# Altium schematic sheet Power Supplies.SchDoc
size 431 x 279 mm; Organization: ORGANIZATION; Address1: ADDRESS 1; Address2: ADDRESS 2; Address3: ADDRESS 3; Address4: ADDRESS 4; Revision: -; ENG_APP_DATE: --/--/--; DSN_APP_DATE: --/--/--; CHK_APP_DATE: --/--/--
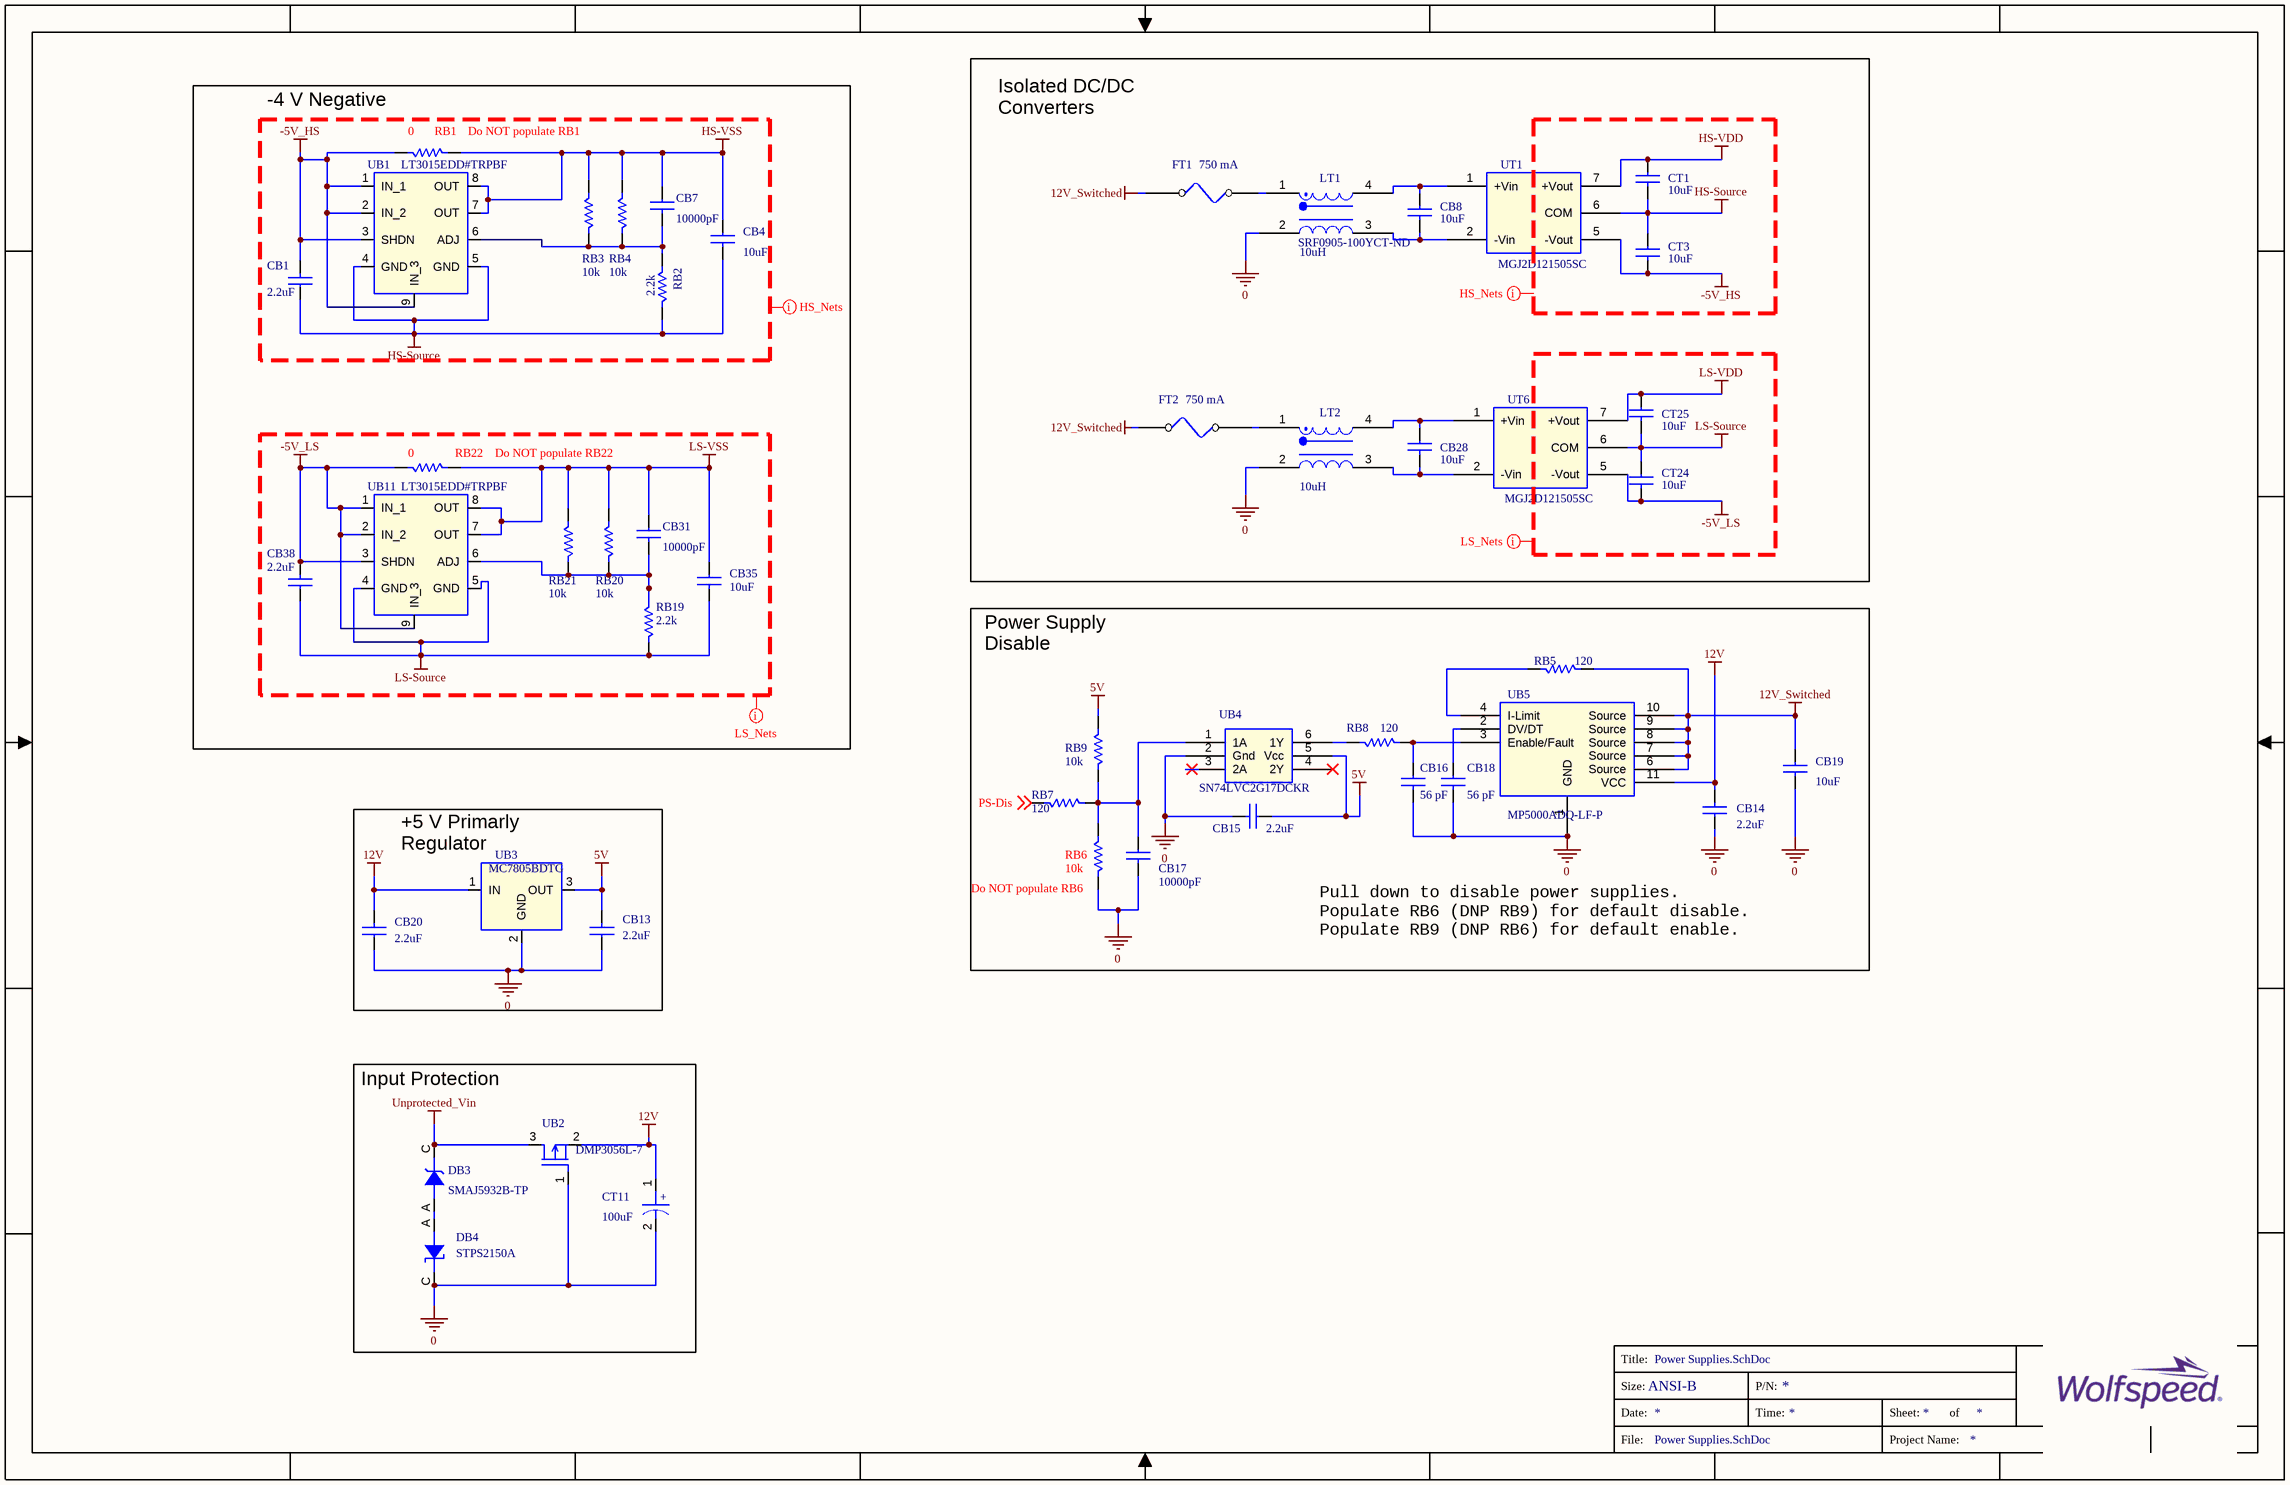
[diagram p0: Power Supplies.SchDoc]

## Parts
CB1  2.2uF  [CAPC1608X90N]
CB4  10uF  [C_1206]
CB7  10000pF  [CAPC1608X90N]
CB8  10uF  [C_1206]
CB13  2.2uF  [CAPC1608X90N]
CB14  2.2uF  [CAPC1608X90N]
CB15  2.2uF  [CAPC1608X90N]
CB16  56 pF  [CAPC1608X90N]
CB17  10000pF  [CAPC1608X90N]
CB18  56 pF  [CAPC1608X90N]
CB19  10uF  [C_1206]
CB20  2.2uF  [CAPC1608X90N]
CB28  10uF  [C_1206]
CB31  10000pF  [CAPC1608X90N]
CB35  10uF  [C_1206]
CB38  2.2uF  [CAPC1608X90N]
CT1  10uF  [C_1206]
CT3  10uF  [C_1206]
CT11  100uF  [CAP_EEE1HA101UP]
CT24  10uF  [C_1206]
CT25  10uF  [C_1206]
DB3  SMAJ5932B-TP  [DIOM4426X24N_DB3]
DB4  STPS2150A  [DIOM4326X26N_DB4]
FT1  750 mA  [FUSE_SMD_SSQ2410]
FT2  750 mA  [FUSE_SMD_SSQ2410]
LT1  10uH  Supplier Part Number 1: SRF0905-100YCT-ND  [SRF0905]
LT2  10uH  [SRF0905]
RB1  0  [RES_2012_SAM]
RB2  2.2k  [RESC1608X55N]
RB3  10k  [RESC1608X55N]
RB4  10k  [RESC1608X55N]
RB5  120  [RESC1608X55N]
RB6  10k  [RESC1608X55N]
RB7  120  [RESC1608X55N]
RB8  120  [RESC1608X55N]
RB9  10k  [RESC1608X55N]
RB19  2.2k  [RESC1608X55N]
RB20  10k  [RESC1608X55N]
RB21  10k  [RESC1608X55N]
RB22  0  [RES_2012_SAM]
UB1  LT3015EDD#TRPBF  [8-WDFN_Exposed_Pad]
UB2  DMP3056L-7  [SOT_23_3]
UB3  MC7805BDTG  [DPAK-3]
UB4  SN74LVC2G17DCKR  [SOT65P210X110-6N_UB4]
UB5  MP5000ADQ-LF-P  [SON50P300X300X100-11N]
UB11  LT3015EDD#TRPBF  [8-WDFN_Exposed_Pad]
UT1  MGJ2D121505SC  [MGJ2D121505SC]
UT6  MGJ2D121505SC  [MGJ2D121505SC]

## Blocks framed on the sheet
Do NOT populate RB6: CB14-CB19 RB5-RB9 UB4 UB5
Input Protection: CT11 DB3 DB4 UB2

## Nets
0: CB13.1 CB14.1 CB15.2 CB16.2 CB17.2 CB18.2 CB19.2 CB20.1 CT11.2 DB4.C LT1.2 LT2.2 RB6.2 UB2.1(G) UB3.2(GND) UB4.2(Gnd) UB5.1(GND)
5V: CB13.2 CB15.1 RB9.1 UB3.3(OUT) UB4.5(Vcc)
12V: CB14.2 CB20.2 CT11.1 UB2.2(S) UB3.1(IN) UB5.11(VCC)
12V_Switched: CB19.1 FT1.1 FT2.1 RB5.1 UB5.6(Source) UB5.7(Source) UB5.8(Source) UB5.9(Source) UB5.10(Source)
-5V_HS: CB1.2 CT3.2 RB1.1 UB1.1(IN_1) UB1.2(IN_2) UB1.3(SHDN) UB1.9(IN_3) UT1.5(-Vout)
-5V_LS: CB38.2 CT24.2 RB22.1 UB11.1(IN_1) UB11.2(IN_2) UB11.3(SHDN) UB11.9(IN_3) UT6.5(-Vout)
HS-Source: CB1.1 CB4.2 CT1.2 CT3.1 RB2.2 UB1.4(GND) UB1.5(GND) UT1.6(COM)
HS-VDD: CT1.1 UT1.7(+Vout)
HS-VSS: CB4.1 CB7.1 RB1.2 RB3.1 RB4.1 UB1.7(OUT) UB1.8(OUT)
LS-Source: CB35.2 CB38.1 CT24.1 CT25.2 RB19.2 UB11.4(GND) UB11.5(GND) UT6.6(COM)
LS-VDD: CT25.1 UT6.7(+Vout)
LS-VSS: CB31.1 CB35.1 RB20.1 RB21.1 RB22.2 UB11.7(OUT) UB11.8(OUT)
Unprotected_Vin: DB3.C UB2.3(D)
PS-Dis: RB7.2 ; off-sheet PS-Dis
NetCB7_2: CB7.2 RB2.1 RB3.2 RB4.2 UB1.6(ADJ)
NetCB8_1: CB8.1 LT1.4 UT1.1(+Vin)
NetCB8_2: CB8.2 LT1.3 UT1.2(-Vin)
NetCB16_1: CB16.1 RB8.1 UB5.3(Enable/Fault)
NetCB17_1: CB17.1 RB6.1 RB7.1 RB9.2 UB4.1(1A)
NetCB18_1: CB18.1 UB5.2(DV/DT)
NetCB28_1: CB28.1 LT2.4 UT6.1(+Vin)
NetCB28_2: CB28.2 LT2.3 UT6.2(-Vin)
NetCB31_2: CB31.2 RB19.1 RB20.2 RB21.2 UB11.6(ADJ)
NetDB3_A: DB3.A DB4.A
NetFT1_2: FT1.2 LT1.1
NetFT2_2: FT2.2 LT2.1
NetRB5_2: RB5.2 UB5.4(I-Limit)
NetRB8_2: RB8.2 UB4.6(1Y)

Not connected (* = marked no-connect by the designer): UB4 3(2A)* 4(2Y)*; UB5 5(NC)

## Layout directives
net class LS_Nets: -5V_LS, LS-Source, LS-VDD, LS-VSS
net class HS_Nets: -5V_HS, HS-Source, HS-VDD, HS-VSS

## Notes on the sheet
- (near RB1) -4 V Negative Regulators
- (near RB1) Do NOT populate RB1
- Isolated DC/DC
  Converters
- Do NOT populate RB22
- Power Supply
  Disable
- (near UB3) +5 V Primarly
  Regulator
- Pull down to disable power supplies.
  Populate RB6 (DNP RB9) for default disable.
  Populate RB9 (DNP RB6) for default enable.

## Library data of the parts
CB1 CB14 CB15 CB20 CB38 = CAP_2.2uF: CAP CER 2.2UF 50V X5R 0603; Company Part Status: Obsolete; Manufacturer PN: GRT188R61H225ME13D; Manufacturer: Murata Electronics North America; CLASS: DISCRETE; Tolerance: 20%
CB4 CB8 CB28 CB35 CT1 CT3 = CAP_10uF: CAP CER 10UF 16V X7R 1206; Company Part Status: New; PART_NUMBER: TMP-885; Manufacturer: Murata Electronics North America; Manufacturer PN: GCM31CR71C106KA64L; Dielectric Type: Capacitors; Tolerance: 10%; CLASS: DISCRETE
CB7 CB17 CB31 = CAP: CAP CER 10000PF 25V 10% X7R 0603; Company Part Status: New; PART_NUMBER: TMP-566; Manufacturer: Samsung Electro-Mechanics America, Inc.; Manufacturer PN: CL10B103KA8NNNC; Dielectric Type: Capacitors; CLASS: DISCRETE
CB13 = CAP_2.2uF: CAP CER 2.2UF 50V X5R 0603; Manufacturer PN: GRT188R61H225ME13D; Manufacturer: Murata Electronics North America; Company Part Status: Obsolete; CLASS: DISCRETE; Tolerance: 20%
CB16 CB18 = CAP_Dup1: CAP CER 56PF 50V C0G/NP0 0603; Manufacturer PN: CL10C560JB8NNNC; Manufacturer: Samsung Electro-Mechanics; CLASS: DISCRETE; Tolerance: 5%; Temperature Coefficient: C0G, NP0; Dielectric Type: Capacitors
CB19 CT24 CT25 = CAP_10uF: CAP CER 10UF 16V X7R 1206; Manufacturer PN: GCM31CR71C106KA64L; Manufacturer: Murata Electronics North America; PART_NUMBER: TMP-885; Company Part Status: New; CLASS: DISCRETE; Tolerance: 10%; Dielectric Type: Capacitors
CT11 = CAP_100uF: CAP ALUM 100UF 20% 50V SMD; Manufacturer PN: EEE-1HA101UP; Manufacturer: Panasonic Electronic Components; PART_NUMBER: TMP-537; CLASS: DISCRETE; Dielectric Type: Aluminum Electrolitic; PCB Footprint: AlumElec_8mmx10_5mm
DB3 = DIODE_ZENER_3: DIODE ZENER 20V 1.5W DO214AC; Manufacturer: Micro Commercial Co; CLASS: DISCRETE; Tolerance: 5%; Max Reverse Leakage Current: 500nA; Impedance: 14R; Element Configuration: Single; Test Current: 18.7mA; PCB Footprint: SOD123
DB4 = DIODE_SCHOTTKY_13: DIODE SCHOTTKY 150V 2A SMA; PART_NUMBER: TMP-523; Manufacturer: STMicroelectronics; Rated Voltage: 820mV @ 2A; CLASS: DISCRETE; Max Reverse Current: 1.5uA; Peak Non-Repetitive Surge Current: 75A; Element Configuration: Single; Forward Voltage: 890mV; Polarity: Standard
FT1 = FUSE: FUSE BOARD MNT 750MA 125VAC/VDC; Manufacturer PN: SSQ 750; Manufacturer: Bel Fuse Inc.; CLASS: DISCRETE
FT2 = FUSE: FUSE BOARD MNT 750MA 125VAC/VDC; Manufacturer: Bel Fuse Inc.; Manufacturer PN: SSQ 750; CLASS: DISCRETE
LT1 LT2 = CM choke - LPD3015_2: INDUCTOR COMMON MODE 10UH 1.6A; Manufacturer: Bourns Inc.; PART_NUMBER: TMP-846; Manufacturer PN: SRF0905-100Y; CLASS: DISCRETE
RB1 = RES_5: RES SMD 0 OHM JUMPER 1/8W 0805; Manufacturer: Samsung Electro-Mechanics; Manufacturer PN: RC2012J000CS; Rated Power: 0.125W, 1/8W; CLASS: DISCRETE; PCB Footprint: RESC2012X70N
RB2 RB19 = RES_2_BOT: RES SMD 2.2K OHM 1% 1/10W 0603; Company Part Status: New; Manufacturer: Yageo; Manufacturer PN: RC0603FR-072K2L; Temperature Coefficient: 100ppm/C; Rated Power: 0.1W, 1/10W; CLASS: DISCRETE
RB3 RB4 RB9 RB20 RB21 = RES: RES SMD 10K OHM 1% 1/10W 0603; Manufacturer PN: ERJ-3EKF1002V; Manufacturer: Panasonic Electronic Components; Company Part Status: New; PART_NUMBER: TMP-788; CLASS: DISCRETE; Rated Power: 0.1W, 1/10W; Temperature Coefficient: 100ppm/C
RB5 RB7 = RES_1: RES SMD 120 OHM 1% 1/10W 0603; Manufacturer PN: RC0603FR-07120RL; Manufacturer: Yageo; PART_NUMBER: TMP-957; Company Part Status: Released; CLASS: DISCRETE; Rated Power: 0.1W, 1/10W; Temperature Coefficient: 100ppm/C
RB6 = RES: RES SMD 10K OHM 1% 1/10W 0603; PART_NUMBER: TMP-788; Company Part Status: New; Manufacturer: Panasonic Electronic Components; Manufacturer PN: ERJ-3EKF1002V; Temperature Coefficient: 100ppm/C; Rated Power: 0.1W, 1/10W; CLASS: DISCRETE
RB8 = RES_1: RES SMD 120 OHM 1% 1/10W 0603; PART_NUMBER: TMP-957; Manufacturer: Yageo; Manufacturer PN: RC0603FR-07120RL; Company Part Status: Released; Temperature Coefficient: 100ppm/C; Rated Power: 0.1W, 1/10W; CLASS: DISCRETE
RB22 = RES_5: RES SMD 0 OHM JUMPER 1/8W 0805; Manufacturer PN: RC2012J000CS; Manufacturer: Samsung Electro-Mechanics; CLASS: DISCRETE; Rated Power: 0.125W, 1/8W; PCB Footprint: RESC2012X70N
UB1 UB11 = LT3015: IC REG LINEAR NEG ADJ 1.5A 8DFN; Manufacturer: Linear Technology/Analog Devices; PACK_SHORT: (IN,IN1,IN2)(OUT,OUT1)(GND,GND1)
UB2 = MOSFET_P_GSD: MOSFET P-CH 30V 4.3A SOT23; Manufacturer: Diodes Incorporated; Polarity: P-Channel; CLASS: DISCRETE
UB3 = MC7805BDTG: IC REG LINEAR 5V 1A DPAK; Company Part Status: Released; Vendor: ON Semiconductor
UB4 = BUFFER_2X_6P: IC BUF NON-INVERT 5.5V SC70-6; Manufacturer: Texas Instruments; Company Part Status: Released; Supply Voltage: 1.65V ~ 5.5V; PCB Footprint: SC70_6
UB5 = MP5000A_5: IC CURR LIMIT SWITCH; Manufacturer: Monolithic Power Systems Inc.; NC: 5; PACK_SHORT: (Source,Source2,Source3,Source4,Source5); Supply Voltage: Not Required; PCB Footprint: 10-VFDFN-thermal-V3_No_Via
UT1 = MGJ2: DC/DC CONVERTER 15V -5V 2W; Manufacturer: Murata Power Solutions Inc.; CLASS: IC; Supply Voltage: 10.8 - 13.2 V
UT6 = MGJ2: DC/DC CONVERTER 15V -5V 2W; Manufacturer: Murata Power Solutions Inc.; Supply Voltage: 10.8 - 13.2 V; CLASS: IC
